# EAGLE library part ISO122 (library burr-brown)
Isolation Amplifier Precision, Lowest Cost
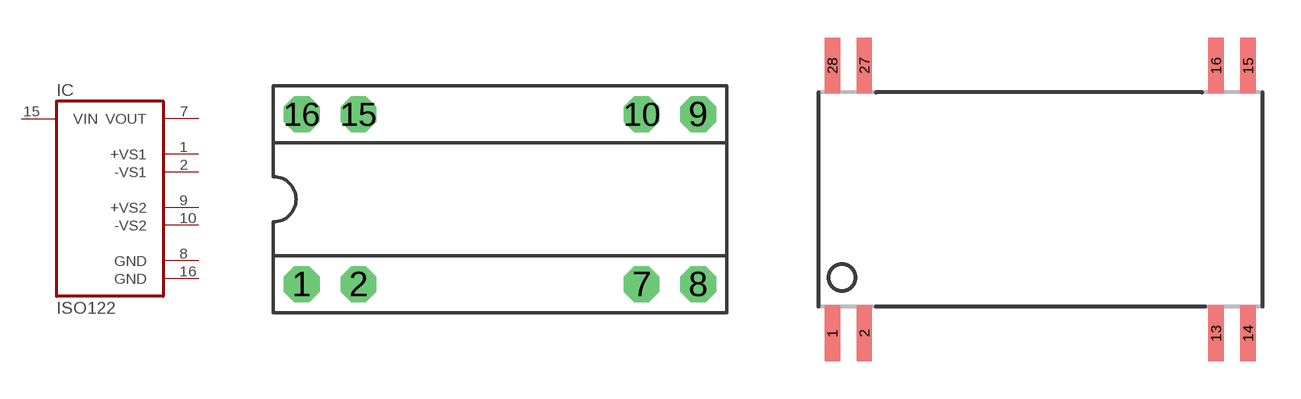
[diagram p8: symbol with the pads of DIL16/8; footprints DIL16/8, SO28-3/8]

Designator prefix IC

## ISO122P (MPN: ISO122P; OC_FARNELL: 1520510; OC_NEWARK: 55M8194)  [DIL16/8]
1  +VS1  pwr
2  -VS1  pwr
7  VOUT  out
8  GND  pwr
9  +VS2  pwr
10  -VS2  pwr
15  VIN  in
16  GND  pwr

## ISO122U (MPN: ISO122UE4; OC_FARNELL: 1206915; OC_NEWARK: 61K0056)  [SO28-3/8]
1  +VS1  pwr
2  -VS1  pwr
13  VOUT  out
14  GND  pwr
15  +VS2  pwr
16  -VS2  pwr
27  VIN  in
28  GND  pwr

## Footprint DIL16/8 (pad centres in mm)
Dual In Line
drill 0.813 pad 1.6 octagon: 1 -8.89,-3.81; 2 -6.35,-3.81; 7 6.35,-3.81; 8 8.89,-3.81; 9 8.89,3.81; 10 6.35,3.81; 15 -6.35,3.81; 16 -8.89,3.81

## Footprint SO28-3/8 (pad centres in mm)
Small Outline Package
smd 0.61 x 2.21: 1 -8.255,-5.315; 2 -6.985,-5.315; 13 6.985,-5.315; 14 8.255,-5.315; 15 8.255,5.315; 16 6.985,5.315; 27 -6.985,5.315; 28 -8.255,5.315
